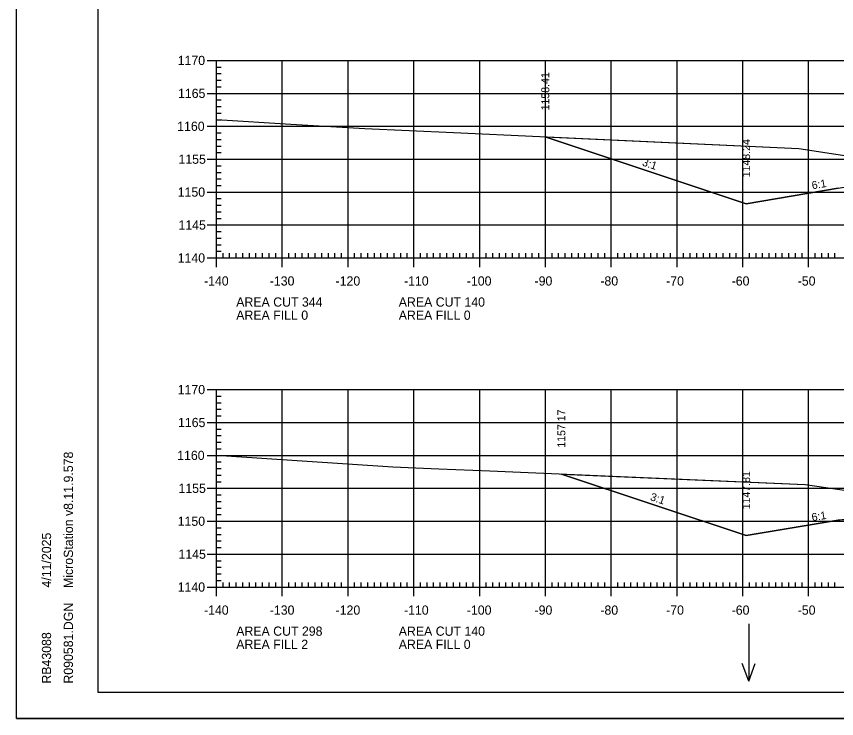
# Model space of a CAD drawing. Extents: x 1322838 to 1324533, y 339903 to 351025.
# Drawn here: x 1323533.3 to 1323658, y 341183.1 to 341289.8 of the extents above; entities that cross this region are included whole.
import ezdxf

# ---------------------------------------------------------------- set-up
doc = ezdxf.new("R2010")
doc.units = 0
for name, color, linetype in [('R_Axis', 7, 'Continuous'), ('R_Axis Annot', 7, 'Continuous'), ('R_Border', 7, 'Continuous'), ('R_Exist Surface', 7, 'Continuous'), ('R_Fin Surface', 7, 'Continuous'), ('R_Fin Surface Annot', 7, 'Continuous'), ('R_Grid', 7, 'Continuous'), ('R_No Plot', 7, 'Continuous'), ('R_Water Annot', 7, 'Continuous')]:
    doc.layers.add(name, color=color, linetype=linetype)

msp = doc.modelspace()

# ---------------------------------------------------------------- linework, layer by layer
at = {"layer": 'R_Axis'}
for p, q in [((1323562.32, 341283.13), (1323565.12, 341283.13)), ((1323563.72, 341253.13), (1323563.72, 341283.13)), ((1323563.72, 341282.13), (1323564.42, 341282.13)), ((1323563.72, 341281.13), (1323564.42, 341281.13)), ((1323563.72, 341280.13), (1323564.42, 341280.13)), ((1323562.32, 341278.13), (1323565.12, 341278.13)), ((1323563.72, 341279.13), (1323564.42, 341279.13)), ((1323563.72, 341277.13), (1323564.42, 341277.13)), ((1323563.72, 341276.13), (1323564.42, 341276.13)), ((1323563.72, 341275.13), (1323564.42, 341275.13)), ((1323562.32, 341273.13), (1323565.12, 341273.13)), ((1323563.72, 341274.13), (1323564.42, 341274.13)), ((1323563.72, 341272.13), (1323564.42, 341272.13)), ((1323563.72, 341271.13), (1323564.42, 341271.13)), ((1323563.72, 341270.13), (1323564.42, 341270.13)), ((1323562.32, 341268.13), (1323565.12, 341268.13)), ((1323563.72, 341269.13), (1323564.42, 341269.13)), ((1323563.72, 341267.13), (1323564.42, 341267.13)), ((1323563.72, 341266.13), (1323564.42, 341266.13)), ((1323563.72, 341265.13), (1323564.42, 341265.13)), ((1323562.32, 341263.13), (1323565.12, 341263.13)), ((1323563.72, 341264.13), (1323564.42, 341264.13)), ((1323563.72, 341262.13), (1323564.42, 341262.13)), ((1323563.72, 341261.13), (1323564.42, 341261.13)), ((1323563.72, 341260.13), (1323564.42, 341260.13)), ((1323563.72, 341259.13), (1323564.42, 341259.13)), ((1323562.32, 341258.13), (1323565.12, 341258.13)), ((1323563.72, 341257.13), (1323564.42, 341257.13)), ((1323563.72, 341256.13), (1323564.42, 341256.13)), ((1323563.72, 341255.13), (1323564.42, 341255.13)), ((1323563.72, 341251.73), (1323563.72, 341254.53)), ((1323573.72, 341251.73), (1323573.72, 341254.53)), ((1323583.72, 341251.73), (1323583.72, 341254.53)), ((1323593.72, 341251.73), (1323593.72, 341254.53)), ((1323603.72, 341251.73), (1323603.72, 341254.53)), ((1323613.72, 341251.73), (1323613.72, 341254.53)), ((1323623.72, 341251.73), (1323623.72, 341254.53)), ((1323633.72, 341251.73), (1323633.72, 341254.53)), ((1323643.72, 341251.73), (1323643.72, 341254.53)), ((1323653.72, 341251.73), (1323653.72, 341254.53)), ((1323563.72, 341254.13), (1323564.42, 341254.13)), ((1323564.72, 341253.13), (1323564.72, 341253.83)), ((1323565.72, 341253.13), (1323565.72, 341253.83)), ((1323566.72, 341253.13), (1323566.72, 341253.83)), ((1323567.72, 341253.13), (1323567.72, 341253.83)), ((1323568.72, 341253.13), (1323568.72, 341253.83)), ((1323569.72, 341253.13), (1323569.72, 341253.83)), ((1323570.72, 341253.13), (1323570.72, 341253.83)), ((1323571.72, 341253.13), (1323571.72, 341253.83)), ((1323572.72, 341253.13), (1323572.72, 341253.83)), ((1323574.72, 341253.13), (1323574.72, 341253.83)), ((1323575.72, 341253.13), (1323575.72, 341253.83)), ((1323576.72, 341253.13), (1323576.72, 341253.83)), ((1323577.72, 341253.13), (1323577.72, 341253.83)), ((1323578.72, 341253.13), (1323578.72, 341253.83)), ((1323579.72, 341253.13), (1323579.72, 341253.83)), ((1323580.72, 341253.13), (1323580.72, 341253.83)), ((1323581.72, 341253.13), (1323581.72, 341253.83)), ((1323582.72, 341253.13), (1323582.72, 341253.83)), ((1323584.72, 341253.13), (1323584.72, 341253.83)), ((1323585.72, 341253.13), (1323585.72, 341253.83)), ((1323586.72, 341253.13), (1323586.72, 341253.83)), ((1323587.72, 341253.13), (1323587.72, 341253.83)), ((1323588.72, 341253.13), (1323588.72, 341253.83)), ((1323589.72, 341253.13), (1323589.72, 341253.83)), ((1323590.72, 341253.13), (1323590.72, 341253.83)), ((1323591.72, 341253.13), (1323591.72, 341253.83)), ((1323592.72, 341253.13), (1323592.72, 341253.83)), ((1323594.72, 341253.13), (1323594.72, 341253.83)), ((1323595.72, 341253.13), (1323595.72, 341253.83)), ((1323596.72, 341253.13), (1323596.72, 341253.83)), ((1323597.72, 341253.13), (1323597.72, 341253.83)), ((1323598.72, 341253.13), (1323598.72, 341253.83)), ((1323599.72, 341253.13), (1323599.72, 341253.83)), ((1323600.72, 341253.13), (1323600.72, 341253.83)), ((1323601.72, 341253.13), (1323601.72, 341253.83)), ((1323602.72, 341253.13), (1323602.72, 341253.83)), ((1323604.72, 341253.13), (1323604.72, 341253.83)), ((1323605.72, 341253.13), (1323605.72, 341253.83)), ((1323606.72, 341253.13), (1323606.72, 341253.83)), ((1323607.72, 341253.13), (1323607.72, 341253.83)), ((1323608.72, 341253.13), (1323608.72, 341253.83)), ((1323609.72, 341253.13), (1323609.72, 341253.83)), ((1323610.72, 341253.13), (1323610.72, 341253.83)), ((1323611.72, 341253.13), (1323611.72, 341253.83)), ((1323612.72, 341253.13), (1323612.72, 341253.83)), ((1323614.72, 341253.13), (1323614.72, 341253.83)), ((1323615.72, 341253.13), (1323615.72, 341253.83)), ((1323616.72, 341253.13), (1323616.72, 341253.83)), ((1323617.72, 341253.13), (1323617.72, 341253.83)), ((1323618.72, 341253.13), (1323618.72, 341253.83)), ((1323619.72, 341253.13), (1323619.72, 341253.83)), ((1323620.72, 341253.13), (1323620.72, 341253.83)), ((1323621.72, 341253.13), (1323621.72, 341253.83)), ((1323622.72, 341253.13), (1323622.72, 341253.83)), ((1323624.72, 341253.13), (1323624.72, 341253.83)), ((1323625.72, 341253.13), (1323625.72, 341253.83)), ((1323626.72, 341253.13), (1323626.72, 341253.83)), ((1323627.72, 341253.13), (1323627.72, 341253.83)), ((1323628.72, 341253.13), (1323628.72, 341253.83)), ((1323629.72, 341253.13), (1323629.72, 341253.83)), ((1323630.72, 341253.13), (1323630.72, 341253.83)), ((1323631.72, 341253.13), (1323631.72, 341253.83)), ((1323632.72, 341253.13), (1323632.72, 341253.83)), ((1323634.72, 341253.13), (1323634.72, 341253.83)), ((1323635.72, 341253.13), (1323635.72, 341253.83)), ((1323636.72, 341253.13), (1323636.72, 341253.83)), ((1323637.72, 341253.13), (1323637.72, 341253.83)), ((1323638.72, 341253.13), (1323638.72, 341253.83)), ((1323639.72, 341253.13), (1323639.72, 341253.83)), ((1323640.72, 341253.13), (1323640.72, 341253.83)), ((1323641.72, 341253.13), (1323641.72, 341253.83)), ((1323642.72, 341253.13), (1323642.72, 341253.83)), ((1323644.72, 341253.13), (1323644.72, 341253.83)), ((1323645.72, 341253.13), (1323645.72, 341253.83)), ((1323646.72, 341253.13), (1323646.72, 341253.83)), ((1323647.72, 341253.13), (1323647.72, 341253.83)), ((1323648.72, 341253.13), (1323648.72, 341253.83)), ((1323649.72, 341253.13), (1323649.72, 341253.83)), ((1323650.72, 341253.13), (1323650.72, 341253.83)), ((1323651.72, 341253.13), (1323651.72, 341253.83)), ((1323652.72, 341253.13), (1323652.72, 341253.83)), ((1323654.72, 341253.13), (1323654.72, 341253.83)), ((1323655.72, 341253.13), (1323655.72, 341253.83)), ((1323656.72, 341253.13), (1323656.72, 341253.83)), ((1323657.72, 341253.13), (1323657.72, 341253.83)), ((1323562.32, 341253.13), (1323565.12, 341253.13)), ((1323563.72, 341253.13), (1323843.72, 341253.13)), ((1323562.32, 341233.13), (1323565.12, 341233.13)), ((1323563.72, 341203.13), (1323563.72, 341233.13)), ((1323563.72, 341232.13), (1323564.42, 341232.13)), ((1323563.72, 341231.13), (1323564.42, 341231.13)), ((1323563.72, 341230.13), (1323564.42, 341230.13)), ((1323563.72, 341229.13), (1323564.42, 341229.13)), ((1323562.32, 341228.13), (1323565.12, 341228.13)), ((1323563.72, 341227.13), (1323564.42, 341227.13)), ((1323563.72, 341226.13), (1323564.42, 341226.13)), ((1323563.72, 341225.13), (1323564.42, 341225.13)), ((1323563.72, 341224.13), (1323564.42, 341224.13)), ((1323562.32, 341223.13), (1323565.12, 341223.13)), ((1323563.72, 341222.13), (1323564.42, 341222.13)), ((1323563.72, 341221.13), (1323564.42, 341221.13)), ((1323563.72, 341220.13), (1323564.42, 341220.13)), ((1323563.72, 341219.13), (1323564.42, 341219.13)), ((1323562.32, 341218.13), (1323565.12, 341218.13)), ((1323563.72, 341217.13), (1323564.42, 341217.13)), ((1323563.72, 341216.13), (1323564.42, 341216.13)), ((1323563.72, 341215.13), (1323564.42, 341215.13)), ((1323563.72, 341214.13), (1323564.42, 341214.13)), ((1323562.32, 341213.13), (1323565.12, 341213.13)), ((1323563.72, 341212.13), (1323564.42, 341212.13)), ((1323563.72, 341211.13), (1323564.42, 341211.13)), ((1323563.72, 341210.13), (1323564.42, 341210.13)), ((1323563.72, 341209.13), (1323564.42, 341209.13)), ((1323562.32, 341208.13), (1323565.12, 341208.13)), ((1323563.72, 341207.13), (1323564.42, 341207.13)), ((1323563.72, 341206.13), (1323564.42, 341206.13)), ((1323563.72, 341205.13), (1323564.42, 341205.13)), ((1323563.72, 341201.73), (1323563.72, 341204.53)), ((1323573.72, 341201.73), (1323573.72, 341204.53)), ((1323583.72, 341201.73), (1323583.72, 341204.53)), ((1323593.72, 341201.73), (1323593.72, 341204.53)), ((1323603.72, 341201.73), (1323603.72, 341204.53)), ((1323613.72, 341201.73), (1323613.72, 341204.53)), ((1323623.72, 341201.73), (1323623.72, 341204.53)), ((1323633.72, 341201.73), (1323633.72, 341204.53)), ((1323643.72, 341201.73), (1323643.72, 341204.53)), ((1323653.72, 341201.73), (1323653.72, 341204.53)), ((1323563.72, 341204.13), (1323564.42, 341204.13)), ((1323564.72, 341203.13), (1323564.72, 341203.83)), ((1323565.72, 341203.13), (1323565.72, 341203.83)), ((1323566.72, 341203.13), (1323566.72, 341203.83)), ((1323567.72, 341203.13), (1323567.72, 341203.83)), ((1323568.72, 341203.13), (1323568.72, 341203.83)), ((1323569.72, 341203.13), (1323569.72, 341203.83)), ((1323570.72, 341203.13), (1323570.72, 341203.83)), ((1323571.72, 341203.13), (1323571.72, 341203.83)), ((1323572.72, 341203.13), (1323572.72, 341203.83)), ((1323574.72, 341203.13), (1323574.72, 341203.83)), ((1323575.72, 341203.13), (1323575.72, 341203.83)), ((1323576.72, 341203.13), (1323576.72, 341203.83)), ((1323577.72, 341203.13), (1323577.72, 341203.83)), ((1323578.72, 341203.13), (1323578.72, 341203.83)), ((1323579.72, 341203.13), (1323579.72, 341203.83)), ((1323580.72, 341203.13), (1323580.72, 341203.83)), ((1323581.72, 341203.13), (1323581.72, 341203.83)), ((1323582.72, 341203.13), (1323582.72, 341203.83)), ((1323584.72, 341203.13), (1323584.72, 341203.83)), ((1323585.72, 341203.13), (1323585.72, 341203.83)), ((1323586.72, 341203.13), (1323586.72, 341203.83)), ((1323587.72, 341203.13), (1323587.72, 341203.83)), ((1323588.72, 341203.13), (1323588.72, 341203.83)), ((1323589.72, 341203.13), (1323589.72, 341203.83)), ((1323590.72, 341203.13), (1323590.72, 341203.83)), ((1323591.72, 341203.13), (1323591.72, 341203.83)), ((1323592.72, 341203.13), (1323592.72, 341203.83)), ((1323594.72, 341203.13), (1323594.72, 341203.83)), ((1323595.72, 341203.13), (1323595.72, 341203.83)), ((1323596.72, 341203.13), (1323596.72, 341203.83)), ((1323597.72, 341203.13), (1323597.72, 341203.83)), ((1323598.72, 341203.13), (1323598.72, 341203.83)), ((1323599.72, 341203.13), (1323599.72, 341203.83)), ((1323600.72, 341203.13), (1323600.72, 341203.83)), ((1323601.72, 341203.13), (1323601.72, 341203.83)), ((1323602.72, 341203.13), (1323602.72, 341203.83)), ((1323604.72, 341203.13), (1323604.72, 341203.83)), ((1323605.72, 341203.13), (1323605.72, 341203.83)), ((1323606.72, 341203.13), (1323606.72, 341203.83)), ((1323607.72, 341203.13), (1323607.72, 341203.83)), ((1323608.72, 341203.13), (1323608.72, 341203.83)), ((1323609.72, 341203.13), (1323609.72, 341203.83)), ((1323610.72, 341203.13), (1323610.72, 341203.83)), ((1323611.72, 341203.13), (1323611.72, 341203.83)), ((1323612.72, 341203.13), (1323612.72, 341203.83)), ((1323614.72, 341203.13), (1323614.72, 341203.83)), ((1323615.72, 341203.13), (1323615.72, 341203.83)), ((1323616.72, 341203.13), (1323616.72, 341203.83)), ((1323617.72, 341203.13), (1323617.72, 341203.83)), ((1323618.72, 341203.13), (1323618.72, 341203.83)), ((1323619.72, 341203.13), (1323619.72, 341203.83)), ((1323620.72, 341203.13), (1323620.72, 341203.83)), ((1323621.72, 341203.13), (1323621.72, 341203.83)), ((1323622.72, 341203.13), (1323622.72, 341203.83)), ((1323624.72, 341203.13), (1323624.72, 341203.83)), ((1323625.72, 341203.13), (1323625.72, 341203.83)), ((1323626.72, 341203.13), (1323626.72, 341203.83)), ((1323627.72, 341203.13), (1323627.72, 341203.83)), ((1323628.72, 341203.13), (1323628.72, 341203.83)), ((1323629.72, 341203.13), (1323629.72, 341203.83)), ((1323630.72, 341203.13), (1323630.72, 341203.83)), ((1323631.72, 341203.13), (1323631.72, 341203.83)), ((1323632.72, 341203.13), (1323632.72, 341203.83)), ((1323634.72, 341203.13), (1323634.72, 341203.83)), ((1323635.72, 341203.13), (1323635.72, 341203.83)), ((1323636.72, 341203.13), (1323636.72, 341203.83)), ((1323637.72, 341203.13), (1323637.72, 341203.83)), ((1323638.72, 341203.13), (1323638.72, 341203.83)), ((1323639.72, 341203.13), (1323639.72, 341203.83)), ((1323640.72, 341203.13), (1323640.72, 341203.83)), ((1323641.72, 341203.13), (1323641.72, 341203.83)), ((1323642.72, 341203.13), (1323642.72, 341203.83)), ((1323644.72, 341203.13), (1323644.72, 341203.83)), ((1323645.72, 341203.13), (1323645.72, 341203.83)), ((1323646.72, 341203.13), (1323646.72, 341203.83)), ((1323647.72, 341203.13), (1323647.72, 341203.83)), ((1323648.72, 341203.13), (1323648.72, 341203.83)), ((1323649.72, 341203.13), (1323649.72, 341203.83)), ((1323650.72, 341203.13), (1323650.72, 341203.83)), ((1323651.72, 341203.13), (1323651.72, 341203.83)), ((1323652.72, 341203.13), (1323652.72, 341203.83)), ((1323654.72, 341203.13), (1323654.72, 341203.83)), ((1323655.72, 341203.13), (1323655.72, 341203.83)), ((1323656.72, 341203.13), (1323656.72, 341203.83)), ((1323657.72, 341203.13), (1323657.72, 341203.83)), ((1323562.32, 341203.13), (1323565.12, 341203.13)), ((1323563.72, 341203.13), (1323843.72, 341203.13))]:
    msp.add_line(p, q, dxfattribs=at)
at = {"layer": 'R_Border'}
for p, q in [((1323545.72, 341187.13), (1323545.72, 341392.59)), ((1323545.72, 341187.13), (1323545.72, 341187.13)), ((1323861.9, 341187.13), (1323545.72, 341187.13))]:
    msp.add_line(p, q, dxfattribs=at)
at = {"layer": 'R_Exist Surface'}
for points in [[(1323563.72, 341274.16), (1323575.02, 341273.47), (1323586.29, 341272.78), (1323599.73, 341272.19), (1323652.24, 341269.76), (1323657.83, 341268.91), (1323667.97, 341267.35)], [(1323563.72, 341223.14), (1323590.52, 341221.38), (1323597.53, 341221.08), (1323605.29, 341220.76), (1323653.2, 341218.73), (1323661.95, 341217.43)]]:
    msp.add_lwpolyline(points, dxfattribs=at)
at = {"layer": 'R_Fin Surface'}
for points in [[(1323613.69, 341271.54), (1323644.22, 341261.37), (1323658.22, 341263.7), (1323658.23, 341263.7), (1323666.22, 341265.03), (1323670.76, 341265.22), (1323672.22, 341265.27), (1323673.18, 341265.29), (1323674.22, 341265.31), (1323703.72, 341265.9), (1323715.25, 341265.67), (1323733.21, 341265.31), (1323733.22, 341265.31), (1323735.22, 341265.27), (1323738.05, 341265.16), (1323741.22, 341265.03), (1323749.21, 341263.7), (1323752.38, 341263.17), (1323763.21, 341261.37), (1323763.22, 341261.37), (1323773.05, 341264.65)], [(1323616.14, 341220.3), (1323644.22, 341210.94), (1323658.22, 341213.27), (1323666.22, 341214.61), (1323669.31, 341214.73), (1323672.22, 341214.85), (1323674.14, 341214.88), (1323674.22, 341214.89), (1323703.72, 341215.48), (1323733.22, 341214.89), (1323734.26, 341214.86), (1323735.22, 341214.85), (1323739.03, 341214.69), (1323741.22, 341214.61), (1323749.21, 341213.27), (1323763.22, 341210.94), (1323766.99, 341212.2), (1323770.21, 341213.27)]]:
    msp.add_lwpolyline(points, dxfattribs=at)
at = {"layer": 'R_Grid'}
for p, q in [((1323563.72, 341283.13), (1323843.72, 341283.13)), ((1323563.72, 341253.13), (1323563.72, 341283.13)), ((1323573.72, 341253.13), (1323573.72, 341283.13)), ((1323583.72, 341253.13), (1323583.72, 341283.13)), ((1323593.72, 341253.13), (1323593.72, 341283.13)), ((1323603.72, 341253.13), (1323603.72, 341283.13)), ((1323613.72, 341253.13), (1323613.72, 341283.13)), ((1323623.72, 341253.13), (1323623.72, 341283.13)), ((1323633.72, 341253.13), (1323633.72, 341283.13)), ((1323643.72, 341253.13), (1323643.72, 341283.13)), ((1323653.72, 341253.13), (1323653.72, 341283.13)), ((1323563.72, 341278.13), (1323843.72, 341278.13)), ((1323563.72, 341273.13), (1323843.72, 341273.13)), ((1323563.72, 341268.13), (1323843.72, 341268.13)), ((1323563.72, 341263.13), (1323843.72, 341263.13)), ((1323563.72, 341258.13), (1323843.72, 341258.13)), ((1323563.72, 341253.13), (1323843.72, 341253.13)), ((1323563.72, 341233.13), (1323843.72, 341233.13)), ((1323563.72, 341203.13), (1323563.72, 341233.13)), ((1323573.72, 341203.13), (1323573.72, 341233.13)), ((1323583.72, 341203.13), (1323583.72, 341233.13)), ((1323593.72, 341203.13), (1323593.72, 341233.13)), ((1323603.72, 341203.13), (1323603.72, 341233.13)), ((1323613.72, 341203.13), (1323613.72, 341233.13)), ((1323623.72, 341203.13), (1323623.72, 341233.13)), ((1323633.72, 341203.13), (1323633.72, 341233.13)), ((1323643.72, 341203.13), (1323643.72, 341233.13)), ((1323653.72, 341203.13), (1323653.72, 341233.13)), ((1323563.72, 341228.13), (1323843.72, 341228.13)), ((1323563.72, 341223.13), (1323843.72, 341223.13)), ((1323563.72, 341218.13), (1323843.72, 341218.13)), ((1323563.72, 341213.13), (1323843.72, 341213.13)), ((1323563.72, 341208.13), (1323843.72, 341208.13)), ((1323563.72, 341203.13), (1323843.72, 341203.13))]:
    msp.add_line(p, q, dxfattribs=at)
at = {"layer": 'R_No Plot'}
msp.add_line((1323533.31, 341183.15), (1323866.65, 341183.15), dxfattribs=at)
for points in [[(1323533.31, 341396.49), (1323866.65, 341396.49), (1323866.65, 341183.15), (1323533.31, 341183.15)], [(1323779.64, 341392.59), (1323799.26, 341392.59), (1323799.26, 341382.71), (1323815.37, 341382.71), (1323838.57, 341382.71), (1323838.57, 341350.04), (1323861.77, 341350.04), (1323861.9, 341187.13), (1323545.72, 341187.13), (1323545.72, 341392.59)], [(1323616.14, 341220.3), (1323653.2, 341218.73), (1323661.95, 341217.43), (1323667.55, 341216.59), (1323681.82, 341215.34), (1323687.89, 341214.82), (1323689.75, 341214.49), (1323693.19, 341213.83), (1323672.22, 341213.55), (1323658.22, 341213.27), (1323644.22, 341210.94), (1323616.14, 341220.3)]]:
    msp.add_lwpolyline(points, close=True, dxfattribs=at)
msp.add_lwpolyline([(1323658.22, 341263.7), (1323644.22, 341261.37), (1323613.69, 341271.54), (1323652.24, 341269.76), (1323657.83, 341268.91), (1323667.97, 341267.35)], dxfattribs=at)
at = {"layer": 'R_Water Annot'}
for p, q in [((1323644.61, 341197.54), (1323644.61, 341188.85)), ((1323644.61, 341188.85), (1323643.64, 341191.51)), ((1323644.61, 341188.85), (1323645.58, 341191.51))]:
    msp.add_line(p, q, dxfattribs=at)

# ---------------------------------------------------------------- texts
at = {"layer": 'R_Axis Annot'}
for s, p in [('1170', (1323557.82, 341282.43)), ('1165', (1323557.87, 341277.43)), ('1160', (1323557.75, 341272.43)), ('1155', (1323557.94, 341267.43)), ('1150', (1323557.82, 341262.43)), ('1145', (1323557.94, 341257.43)), ('1140', (1323557.82, 341252.43)), ('-140', (1323561.82, 341248.93)), ('-130', (1323571.82, 341248.93)), ('-120', (1323581.82, 341248.93)), ('-110', (1323592.22, 341248.93)), ('-100', (1323601.77, 341248.93)), ('-90', (1323612.06, 341248.93)), ('-80', (1323622.06, 341248.93)), ('-70', (1323632.06, 341248.93)), ('-60', (1323642.02, 341248.93)), ('-50', (1323652.06, 341248.93)), ('AREA CUT 344', (1323566.72, 341245.73)), ('AREA CUT 140', (1323591.42, 341245.73)), ('AREA FILL 0', (1323566.72, 341243.73)), ('AREA FILL 0', (1323591.42, 341243.73)), ('1170', (1323557.82, 341232.43)), ('1165', (1323557.87, 341227.43)), ('1160', (1323557.75, 341222.43)), ('1155', (1323557.94, 341217.43)), ('1150', (1323557.82, 341212.43)), ('1145', (1323557.94, 341207.43)), ('1140', (1323557.82, 341202.43)), ('-140', (1323561.82, 341198.93)), ('-130', (1323571.82, 341198.93)), ('-120', (1323581.82, 341198.93)), ('-110', (1323592.22, 341198.93)), ('-100', (1323601.77, 341198.93)), ('-90', (1323612.06, 341198.93)), ('-80', (1323622.06, 341198.93)), ('-70', (1323632.06, 341198.93)), ('-60', (1323642.02, 341198.93)), ('-50', (1323652.06, 341198.93)), ('AREA CUT 298', (1323566.72, 341195.73)), ('AREA CUT 140', (1323591.42, 341195.73)), ('AREA FILL 2', (1323566.72, 341193.73)), ('AREA FILL 0', (1323591.42, 341193.73))]:
    msp.add_text(s, height=1.4, dxfattribs=at).set_placement(p)
at = {"layer": 'R_Border'}
for s, p in [('MicroStation v8.11.9.578', (1323541.91, 341202.99)), ('4/11/2025', (1323538.58, 341203.06)), ('R090581.DGN', (1323541.91, 341188.46)), ('RB43088', (1323538.58, 341188.46))]:
    msp.add_text(s, height=1.4, rotation=90, dxfattribs=at).set_placement(p)
at = {"layer": 'R_Fin Surface Annot'}
for s, rotation, p in [('1158.41', 90, (1323614.29, 341275.54)), ('1148.24', 90, (1323644.82, 341265.37)), ('3:1', 341.5657, (1323628.32, 341267.19)), ('6:1', 9.4631, (1323654.29, 341263.55)), ('1157.17', 90, (1323616.74, 341224.3)), ('1147.81', 90, (1323644.82, 341214.94)), ('3:1', 341.5645, (1323629.55, 341216.35)), ('6:1', 9.4631, (1323654.28, 341213.12))]:
    msp.add_text(s, height=1.2, rotation=rotation, dxfattribs=at).set_placement(p)

doc.saveas('drawing.dxf')
